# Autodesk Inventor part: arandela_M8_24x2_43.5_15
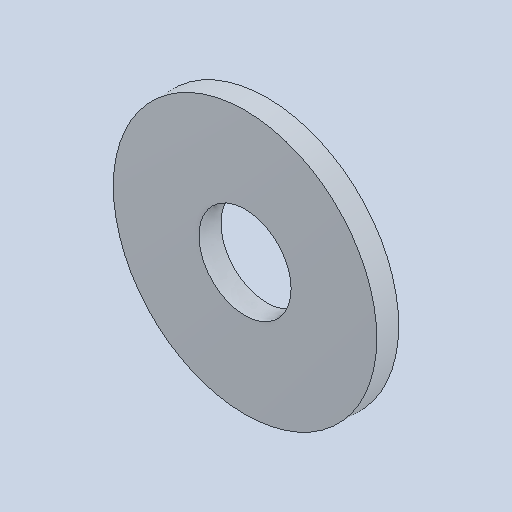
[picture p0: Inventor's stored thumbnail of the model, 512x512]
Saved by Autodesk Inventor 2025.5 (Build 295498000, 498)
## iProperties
Created: 2026-10
Part Number: arandela_M8_24x2_43.5_15
Material: Genérico
Document SubType Name: Modeling
Designer: Luis M
Density: 1 g/cm^3
Appearance: Valor por defecto
Author: Luis M
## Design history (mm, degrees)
feature "Base1"
node "Sólido1"
